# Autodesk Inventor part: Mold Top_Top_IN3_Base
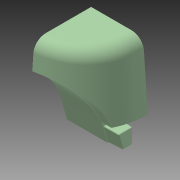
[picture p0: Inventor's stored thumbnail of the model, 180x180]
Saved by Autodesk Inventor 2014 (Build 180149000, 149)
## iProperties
Created: 2009-12
Part Number: Mold Top_Top_IN3_Base
Document SubType Name: Modeling
Designer: gaom
Density: 1 g/cm^3
Material: Generic
Appearance: Green Pastel
Author: gaom
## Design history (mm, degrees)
node "Mold Top_Top_IS" dims "d0" = 10
  sketch "Sketch2"
    geometry: L1 (-2.617, 1.929)-(-2.617, 0.854) reference; L2 (-2.471, 0.66)-(-0.663, 0.146) reference; L3 (0, 0)-(0, 2.033) reference; L4 (-0.609, 2.154)-(-2.415, 2.154) reference; L5 (-0.609, 2.154)-(0, 2.154) reference; L6 (0, 2.154)-(0, 3.654) reference; L7 (0, 3.654)-(8.5, 3.654) reference; L8 (8.5, 3.654)-(8.5, -1.919) reference; L9 (6.5, -3.919)-(4.802, -3.919) reference; L10 (4.802, -3.919)-(4.802, -3.419) reference; L11 (-0.663, 0.146)-(0.014, -0.047) reference; A1 r 2 centre (6.5, -1.919) between (6.5, -3.919) and (8.5, -1.919) reference; A2 r 8.878 centre (-2.418, -8.586) between (4.802, -3.419) and (0.014, -0.047) reference; 3 further points; 2 other entities
    constraints: 2 other
workplane "Work Plane3"
sketch "Sketch7"
  geometry: L1 (-1.929, -2.617)-(-0.854, -2.617) reference; L2 (-0.66, -2.471)-(-0.146, -0.663) reference; L3 (-2.154, -0.609)-(-2.154, -2.415) reference; L4 (-2.154, -0.609)-(-2.154, 0) reference; L5 (-2.154, 0)-(-3.654, 0) reference; L6 (-3.654, 0)-(-3.654, 8.5) reference; L7 (-3.654, 8.5)-(1.919, 8.5) reference; L8 (3.919, 6.5)-(3.919, 4.802) reference; L9 (3.919, 4.802)-(3.419, 4.802) reference; L10 (-0.146, -0.663)-(0.047, 0.014) reference; A1 r 2 centre (1.919, 6.5) between (3.919, 6.5) and (1.919, 8.5) reference; A2 r 8.878 centre (8.586, -2.418) between (3.419, 4.802) and (0.047, 0.014) reference; 3 further points; 2 other entities
  constraints: 2 other
feature "Surface3"
extrude "Extrusion3" join sketch "Sketch7" stored distance "d10" = 0.13; taper "d11" = 0 deg
sketch "Sketch2_1"
  geometry: L1 (-2.617, 1.929)-(-2.617, 0.854) reference; L2 (-2.471, 0.66)-(-0.663, 0.146) reference; L3 (0, 0)-(0, 2.033) reference; L4 (-0.609, 2.154)-(-2.415, 2.154) reference; L5 (-0.609, 2.154)-(0, 2.154) reference; L6 (0, 2.154)-(0, 3.654) reference; L7 (0, 3.654)-(8.5, 3.654) reference; L8 (8.5, 3.654)-(8.5, -1.919) reference; L9 (6.5, -3.919)-(4.802, -3.919) reference; L10 (4.802, -3.919)-(4.802, -3.419) reference; L11 (-0.663, 0.146)-(0.014, -0.047) reference; A1 r 2 centre (6.5, -1.919) between (6.5, -3.919) and (8.5, -1.919) reference; A2 r 8.878 centre (-2.418, -8.586) between (4.802, -3.419) and (0.014, -0.047) reference; 3 further points; 2 other entities
  constraints: 2 other
sketch "Sketch2_2"
  geometry: L1 (-2.617, 1.929)-(-2.617, 0.854) reference; L2 (-2.471, 0.66)-(-0.663, 0.146) reference; L3 (0, 0)-(0, 2.033) reference; L4 (-0.609, 2.154)-(-2.415, 2.154) reference; L5 (-0.609, 2.154)-(0, 2.154) reference; L6 (0, 2.154)-(0, 3.654) reference; L7 (0, 3.654)-(8.5, 3.654) reference; L8 (8.5, 3.654)-(8.5, -1.919) reference; L9 (6.5, -3.919)-(4.802, -3.919) reference; L10 (4.802, -3.919)-(4.802, -3.419) reference; L11 (-0.663, 0.146)-(0.014, -0.047) reference; A1 r 2 centre (6.5, -1.919) between (6.5, -3.919) and (8.5, -1.919) reference; A2 r 8.878 centre (-2.418, -8.586) between (4.802, -3.419) and (0.014, -0.047) reference; 3 further points; 2 other entities
  constraints: 2 other
body "Solid6"
body "Srf3"
other parameters: "d9" = 0
